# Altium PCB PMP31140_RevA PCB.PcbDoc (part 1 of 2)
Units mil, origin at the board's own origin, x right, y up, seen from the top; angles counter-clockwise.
Board outline 6181.25 x 1625 mil, 2 copper layers (Top Layer, Bottom Layer), stack 62 mil thick; 98 components, 49 nets, 210 pads, 6 vias.
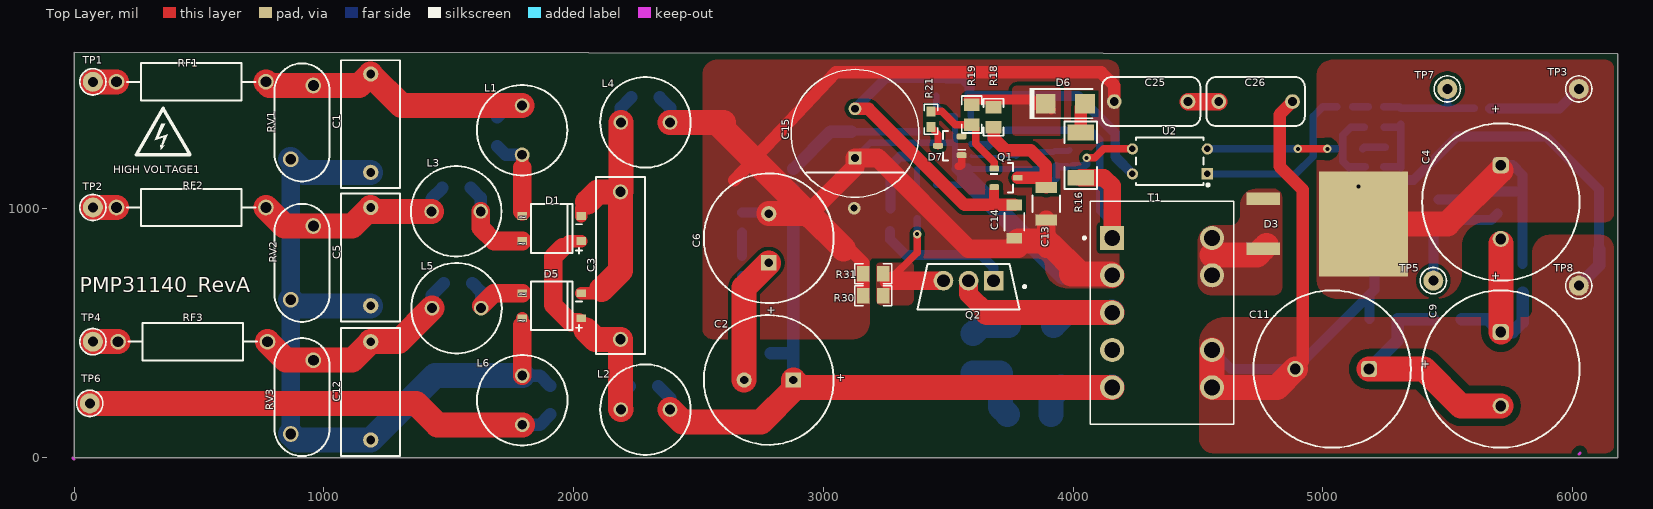
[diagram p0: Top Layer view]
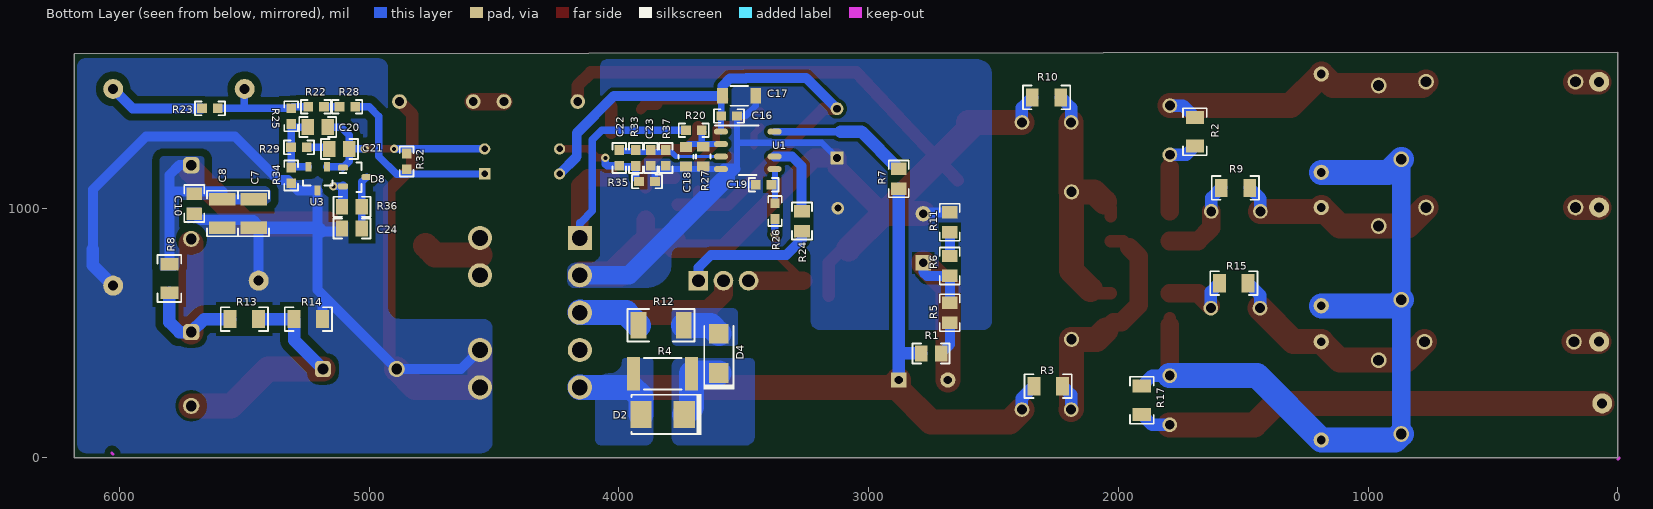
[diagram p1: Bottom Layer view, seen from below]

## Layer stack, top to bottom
Top Solder: solder mask 0.4, Solder Resist, Dk 3.5
Top Layer: signal copper 1.4
Dielectric1: core 59.2, FR-4, Dk 4.8
Bottom Layer: signal copper 1.4
Bottom Solder: solder mask 0.4, Solder Resist, Dk 3.5

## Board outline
0,0 0,1625 6181.25,1618.75 6181.25,1617.36 6181.25,0

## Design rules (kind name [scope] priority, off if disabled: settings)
AcuteAngle [All] p1: minimum=4.50000000000000E+0001 checktracksonly=FALSE
AssemblyTestPointUsage [All] p1: valid=2
Clearance "Schematic Clearance Constraint" [InNet('NetC3_1')] p1: gap=25 ignorepadtopadclearanceinfootprint=FALSE except(0: Arc-Hole Track-Hole SMDPad-Hole THPad-Hole Via-Hole Fill-Hole Poly-Hole Region-Hole Text-Hole)
Clearance "Clearance_PGND NETC17_2" [InNet('PGND') vs InNet('NetC17_2')] p2: gap=10 ignorepadtopadclearanceinfootprint=FALSE
Clearance "Clearance_PGND NETC9_1" [InNet('PGND') vs InNet('NetC13_2')] p3: gap=5 ignorepadtopadclearanceinfootprint=FALSE
Clearance Clearance_PGND [InNet('PGND')] p4: gap=15 ignorepadtopadclearanceinfootprint=FALSE
Clearance Clearance_Keepouts [((IsTrack Or IsArc) And Not InPoly) And IsFree and IsKeepOut vs ((IsTrack Or IsArc) And Not InPoly) And IsFree and IsKeepOut] p5: gap=0 ignorepadtopadclearanceinfootprint=FALSE
Clearance Clearance_BoardEdge_MountingHoles [OnCopper and InComponentClass('Mounting Holes') vs IsKeepOut] p6: gap=40 ignorepadtopadclearanceinfootprint=FALSE except(0: Arc-Hole Track-Hole SMDPad-Hole THPad-Hole Via-Hole Fill-Hole Poly-Hole Region-Hole Text-Hole)
Clearance Clearance_BoardEdge_Poly [OnCopper and InPoly vs IsKeepOut] p7: gap=25 ignorepadtopadclearanceinfootprint=FALSE except(0: Arc-Hole Track-Hole SMDPad-Hole THPad-Hole Via-Hole Fill-Hole Poly-Hole Region-Hole Text-Hole)
Clearance Clearance_BoardEdge [OnCopper and Not InComponentClass('Logo') and not InComponentClass('FiducialMark') and not InRegion(1000,500,4000,800) and Not IsKeepout vs IsKeepOut] p8: gap=75 ignorepadtopadclearanceinfootprint=FALSE except(0: Arc-Hole Track-Hole SMDPad-Hole THPad-Hole Via-Hole Fill-Hole Poly-Hole Region-Hole Text-Hole)
Clearance Clearance_Poly [InPolygon] p9: gap=30 ignorepadtopadclearanceinfootprint=FALSE
Clearance [All] p10: gap=7 ignorepadtopadclearanceinfootprint=FALSE
ComponentClearance ComponentClearance_104 [InComponent('TP104')] p1: gap=1 collisioncheckmode=3 verticalgap=1 showdistances=FALSE
ComponentClearance ComponentClearance_103 [InComponent('TP103')] p2: gap=1 collisioncheckmode=3 verticalgap=1 showdistances=FALSE
ComponentClearance ComponentClearance_102 [InComponent('TP102')] p3: gap=1 collisioncheckmode=3 verticalgap=1 showdistances=FALSE
ComponentClearance ComponentClearance_TP101 [InComponent('TP101')] p4: gap=1 collisioncheckmode=3 verticalgap=1 showdistances=FALSE
ComponentClearance ComponentClearance_MountingHoles_FiducialMarks [InComponentClass('Mounting Holes') vs InComponentClass('FiducialMark')] p5: gap=50 collisioncheckmode=3 verticalgap=10 showdistances=FALSE
ComponentClearance ComponentClearance_Shunt [InComponentClass('Header') vs InComponentClass('Shunt')] p6: gap=0 collisioncheckmode=3 verticalgap=0 showdistances=FALSE
ComponentClearance ComponentClearance_Logo [InComponentClass('Logo')] p7: gap=50 collisioncheckmode=3 verticalgap=10 showdistances=FALSE
ComponentClearance ComponentClearance_ScrewToNut [(HasFootprint('NY PMS 440 0025 PH')) vs (HasFootprint('Keystone_1902C'))] p8: gap=5 collisioncheckmode=3 verticalgap=10 showdistances=FALSE
ComponentClearance ComponentClearance_MountingHoles [InComponentClass('Mounting Holes')] p9: gap=250 collisioncheckmode=3 verticalgap=100000 showdistances=FALSE
ComponentClearance ComponentClearance_SmallPassives [HasFootprint('0201*') or HasFootprint('0402*') or HasFootprint('0508') or HasFootprint('0603*') or HasFootprint('0612') or HasFootprint('0805*') or HasFootprint('0815*') or HasFootprint('0830*') or HasFootprint('1206*') or HasFootprint('1210*') or HasFootprint('1808*') or HasFootprint('1812*') or HasFootprint('1825*') or HasFootprint('2010*') or HasFootprint('2220*') or HasFootprint('2225*') or HasFootprint('2512*') or HasFootprint('2728*') or HasFootprint('3518*') vs HasFootprint('0201*') or HasFootprint('0402*') or HasFootprint('0508') or HasFootprint('0603*') or HasFootprint('0612') or HasFootprint('0805*') or HasFootprint('0815*') or HasFootprint('0830*') or HasFootprint('1206*') or HasFootprint('1210*') or HasFootprint('1808*') or HasFootprint('1812*') or HasFootprint('1825*') or HasFootprint('2010*') or HasFootprint('2220*') or HasFootprint('2225*') or HasFootprint('2512*') or HasFootprint('2728*') or HasFootprint('3518*')] p10: gap=10 collisioncheckmode=3 verticalgap=10 showdistances=FALSE
ComponentClearance ComponentClearance_THtoSMT [IsThruComponent vs IsSMTComponent] p11: gap=20 collisioncheckmode=3 verticalgap=30 showdistances=FALSE
ComponentClearance ComponentClearance_THtoTH [IsThruComponent vs IsThruComponent] p12: gap=20 collisioncheckmode=3 verticalgap=30 showdistances=FALSE
ComponentClearance [All] p13: gap=20 collisioncheckmode=3 verticalgap=10 showdistances=FALSE
DiffPairsRouting [All] p1: maxlimit=100 minlimit=10 mostfreqgap=10 toplayer_minwidth=15 toplayer_maxwidth=15 toplayer_prefwidth=15 bottomlayer_minwidth=15 bottomlayer_maxwidth=15 bottomlayer_prefwidth=15 maxuncoupledlength=1000
FabricationTestPointUsage TestPointUsage [All] p1: valid=2 allowmultiple=FALSE
FabricationTestpoint Testpoint [All] p1: side=3 testpointundercomponent=TRUE minsize=40 maxsize=100 preferedsize=60 minholesize=0 maxholesize=40 preferedholesize=32 testpointgrid=1 allowsidetop=TRUE allowsidebottom=TRUE usegrid=TRUE gridtolerance=0.01
FanoutControl Fanout_LCC [IsLCC] p1: bgadir=Out bgaviamode=Centered fanoutstyle=Auto fanoutdirection=Alternating viagrid=1 // Fanout_LCC (Default Rule)
FanoutControl Fanout_BGA [IsBGA] p2: bgadir=Out bgaviamode=Centered fanoutstyle=Auto fanoutdirection=Alternating viagrid=1 // Fanout_BGA (Default Rule)
FanoutControl Fanout_Default [All] p4: bgadir=Out bgaviamode=Centered fanoutstyle=Auto fanoutdirection=Alternating viagrid=1 // Fanout_Default (Default Rule)
FanoutControl Fanout_Small [(CompPinCount < 5)] p5: bgadir=Out bgaviamode=Centered fanoutstyle=Auto fanoutdirection=OutThenIn viagrid=1 // Fanout_Small (Default Rule)
Height [All] p1: minheight=0 maxheight=2000 prefheight=500
HoleSize [All] p1: absolutevalues=TRUE maxlimit=251 minlimit=8 maxpercent=80.000 minpercent=20.000
MinimumAnnularRing MinimumAnnularRing_ThermalPadVias [IsVia and InAnyComponent] p1: minimumring=5.91
MinimumAnnularRing [All] p2: minimumring=9
MinimumSolderMaskSliver MinimumSolderMaskSliver_Logo [InComponentClass('Logo') vs InComponentClass('Logo')] p1: minsoldermaskwidth=0.7
MinimumSolderMaskSliver [All] p2: minsoldermaskwidth=3.94
PlaneConnect [All] p1: planeconnectstyle=Direct reliefexpansion=10 reliefentries=4 reliefconductorwidth=10 reliefairgap=10
PolygonConnect [All] p1: connectstyle=Direct reliefconductorwidth=10 reliefentries=4 polygonreliefangle="90 Angle" airgapwidth=10
RoutingVias ThermalPadVias [IsVia and InAnyComponent] p1: holewidth=7.87 width=19.68 viastyle="Through Hole" minholewidth=7.87 minwidth=19.68 maxholewidth=12.99 maxwidth=23.62
RoutingVias [All] p2: holewidth=16 width=34 viastyle="Through Hole" minholewidth=7.87 minwidth=26 maxholewidth=40 maxwidth=65
SilkToBoardRegionClearance [Not ((IsComment or IsDesignator) And (Hide <> 'False')) and not InRegion(1000,500,4000,800)] p1:
SilkToSilkClearance SilkToSilkClearance_Pb-FreeLogo [(HasFootprint('Pb-Free_Overlay_Medium') OR HasFootprint('Pb-Free_Overlay_Small')) vs (HasFootprint('Pb-Free_Overlay_Medium') OR HasFootprint('Pb-Free_Overlay_Small'))] p1: silktosilkclearance=0
SilkToSilkClearance [All] p2: silktosilkclearance=0
SilkToSolderMaskClearance SilkToComonentPadClearance [IsPad and InAnycomponent] p1: minsilkscreentomaskgap=0 clearancetoexposedcopper=TRUE
SilkToSolderMaskClearance "Silk to Solder Mask Opening" [All] p2: minsilkscreentomaskgap=4 clearancetoexposedcopper=FALSE
SolderMaskExpansion [All] p1: expansion=1.97 istentingtop=FALSE
Width [All] p1: maxlimit=200 minlimit=6 preferedwidth=10 checkconnectedcopper=TRUE
14 further rules are at their usual default settings.

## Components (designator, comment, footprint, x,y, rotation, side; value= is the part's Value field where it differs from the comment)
C1 "B32921C3104M" B32921_1300x1200x600 1187.5,1340.6 r270 top value=DNP
C2 "EKXG401ELL220MK20S" KXG_1250x2000 2781.25,312.5 r180 top value=22uF
C3 "B32652A0103K" B32652A_500x1050x1800 2187.5,770.28 r90 top value=0.01uF
C4 "SCCU25B256SRB" SCC_1600x2650 5712.5,1024.85 r270 top value=25F
C5 "B32921C3104M" B32921_1300x1200x600 1187.5,806.25 r270 top value=DNP
C6 "EKXG401ELL220MK20S" KXG_1250x2000 2781.25,879.68 r90 top value=22uF
C7 "GRM32ER71A476KE15L" 1210_270 5462.5,978.75 r270 bottom value=47uF
C8 "GRM32ER71A476KE15L" 1210_270 5587.5,978.75 r270 bottom value=47uF
C9 "SCCU25B256SRB" SCC_1600x2650 5712.5,356.25 r270 top value=25F
C10 "GRM21BR71C105KA01L" 0805_HV 5700,1018.75 r270 bottom value=1uF
C11 "SCCU25B256SRB" SCC_1600x2650 5037.5,356.25 r180 top value=25F
C12 "B32921C3104M" B32921_1300x1200x600 1187.5,268.75 r270 top value=DNP
C13 "C3225X7R1H475K250AB" 1210_280 3892.68,1018.19 r270 top value=4.7uF
C14 "C3216X7R1H475K160AC" 1206_180 3764.38,946.49 r270 top value=DNP
C15 "ECA-1HM102" FP-ECA-1HM102_RADIAL-MFG 3126.74,1299.89 r90 top
C16 "06035C104KAT2A" 0603 3558.96,1369.34 r180 bottom value=0.1uF
C17 "C3216X7R1H475K160AC" 1206_180 3518.75,1450 r180 bottom value=2.2uF
C18 "DNP" 0805_HV1 3731.5,1206.25 r270 bottom
C19 "Used in BOM report" 0603 3420.51,1094.34 r0 bottom value=DNP
C20 "CC0805KRX7R9BB682" 0805_HV 5206.25,1325 r180 bottom value=6800pF
C21 "Used in BOM report" 0805_HV 5119,1237.5 r0 bottom value=DNP
C22 "06035C333JAT2A" 0603 3998.28,1201.46 r90 bottom value=0.047uF
C23 "GRM188R71H222KA01D" 0603 3872.51,1201.46 r270 bottom value=2200pF
C24 "GRM21BR71E105KA99L" 0805_HV 5068.75,918.75 r0 bottom value=2.2uF
C25 "DE2E3KY472MB3BM02F" KY_1000x500x1300 4312.5,1427.1 r180 top value=4700pF
C26 "DE2E3KY472MB3BM02F" KY_1000x500x1300 4730.84,1427.1 r180 top value=4700pF
D1 "MB8S-TP" MBS-1 1912.5,918.75 r180 top value=800V
D2 "Used in BOM report" SMB 3825,175 r0 bottom value=130V
D3 "STPS8H100G-TR" DDPAK 5006.99,937.5 r0 top value=100V
D4 "US1K-13-F" SMA 3600,418.75 r90 bottom value=800V
D5 "MB8S-TP" MBS-1 1912.5,609.4 r180 top value=800V
D6 "ES1D-13-F" SMA 3968.75,1418.75 r0 top value=200V
D7 "MMBZ5248BLT1G" SOT-23 3506.25,1250 r180 top value=18V
D8 "BAT54S-7-F" SOT-23 5057.7,1125 r180 bottom value=30V
"HIGH VOLTAGE1" "DANGER HIGH VOLTAGE" IEC_HighVoltage_Small 356.25,1302.51 r0 top
L1 "744732331" WE-TI_8075_STU 1793.75,1312.5 r270 top value=SHORT
L2 "744732331" WE-TI_8075_STU 2287.5,193.75 r0 top value=330uH
L3 "744732331" WE-TI_8075_STU 1529.68,987.5 r0 top value=SHORT
L4 "744732331" WE-TI_8075_STU 2287.5,1343.75 r0 top value=330uH
L5 "744732331" WE-TI_8075_STU 1531.25,600 r0 top value=SHORT
L6 "744732331" WE-TI_8075_STU 1794.39,231.25 r90 top value=SHORT
Q1 "FMMT451" SOT-23 3731.25,1121.95 r0 top value="60 V"
Q2 "STP7N105K5" FP-STP7N105K5_TO-220AB-MFG 3581.25,685.93 r270 top
R1 "CRCW08051M50JNEA" 0805_HV 2750,418.75 r0 bottom value=2.0Meg
R2 "CRCW120610K0JNEA" 1206 1693.75,1306.25 r270 bottom value=DNP
R3 "CRCW120610K0JNEA" 1206 2281.25,287.5 r0 bottom value=10k
R4 "Used in BOM report" 2512 3825,337.5 r0 bottom value=DNP
R5 "CRCW08051M50JNEA" 0805_HV 2675,581.25 r270 bottom value=2.0Meg
R6 "CRCW08051M50JNEA" 0805_HV 2675,768.75 r270 bottom value=2.0Meg
R7 "CRCW080530K0JNEA" 0805_HV 2879.68,1117.59 r270 bottom value=0
R8 "CRCW12061K00JNEA" 1206 5800,718.75 r90 bottom value=1.0k
R9 "CRCW120610K0JNEA" 1206 1531.25,1081.25 r0 bottom value=DNP
R10 "CRCW120610K0JNEA" 1206 2287.5,1443.75 r0 bottom value=10k
R11 "CRCW08051M50JNEA" 0805_HV 2675,943.75 r270 bottom value=2.0Meg
R12 "CRCW2010200RFKEF" 2010 3831.25,531.25 r180 bottom value=200
R13 "CRCW12061K00JNEA" 1206 5500,556.25 r0 bottom value=1.0k
R14 "CRCW12061K00JNEA" 1206 5243.65,556.25 r0 bottom value=1.0k
R15 "CRCW120610K0JNEA" 1206 1537.5,700 r0 bottom value=DNP
R16 "CRCW2010100RJNEF" 2010 4031.25,1212.5 r90 top value=100
R17 "CRCW120610K0JNEA" 1206 1906.25,231.25 r90 bottom value=DNP
R18 "CRCW080510R0FKEA" 0805_HV 3681.64,1364.55 r90 top value=10.0
R19 "CRCW0805200KFKEA" 0805_HV 3593.75,1375 r90 top value=200k
R20 "CRCW0603348KFKEA" 0603 3700,1312.5 r0 bottom value=348k
R21 "Used in BOM report" 0603 3431.25,1356.5 r90 top value=0
R22 "CRCW06030000Z0EA" 0603 5212.5,1406.25 r0 bottom value=0
R23 "CRCW060349R9FKEA" 0603 5637.5,1400 r180 bottom value=49.9
R24 "RC0805FR-0710RL" 0805_HV 3266.96,948.72 r270 bottom value=10.0
R25 "CRCW060349K9FKEA" 0603 5312.5,1368.75 r90 bottom value=49.9k
R26 "CRCW06031K69FKEA" 0603 3375,988.72 r270 bottom value=1.69k
R27 "CRCW080556K2FKEA" 0805_HV1 3662.5,1206.84 r270 bottom value=56.2k
R28 "CRCW06031K50FKEA" 0603 5087.5,1406.25 r0 bottom value=1.50k
R29 "Used in BOM report" 0603 5281.25,1243.75 r180 bottom value=DNP
R30 "ERJ-6RQF2R2V" 0805_HV 3200,650 r0 top value=2.20
R31 "ERJ-6RQF2R2V" 0805_HV 3200,737.5 r0 top value=2.20
R32 "Used in BOM report" 0603 4850,1187.36 r270 bottom value=DNP
R33 "CRCW060330K1FKEA" 0603 3931.99,1201.09 r270 bottom value=100k
R34 "CRCW060330K9FKEA" 0603 5312.5,1131.25 r90 bottom value=30.9k
R35 "Used in BOM report" 0603 3887.5,1107.32 r180 bottom value=DNP
R36 "CRCW0805100KFKEA" 0805_HV 5068.75,1006.25 r180 bottom value=100k
R37 "CRCW060310K0FKEA" 0603 3812.5,1201.46 r90 bottom value=22.1k
RF1 "SPP1UL1R00JLF" SPP_1020x380 468.75,1506.25 r180 top value=1.0
RF2 "SPP1UL1R00JLF" SPP_1020x380 468.75,1003.1 r180 top value=1.0
RF3 "SPP1UL1R00JLF" SPP_1020x380 475,465.6 r180 top value=1.0
RV1 "B72210S2301K101" EPCOS_B72210S2301K101 912.5,1343.75 r90 top value=300VAC
RV2 "B72210S2301K101" EPCOS_B72210S2301K101 912.5,781.25 r90 top value=300VAC
RV3 "B72210S2301K101" EPCOS_B72210S2301K101 912.5,243.75 r90 top value=300VAC
T1 "750319952r00" FP-750319952r00_PTH10_14MM6_22MM7-MFG 4356.25,581.85 r0 top
TP1 "5000" Keystone5000 75,1506.25 r90 top
TP2 "5000" Keystone5000 75,1003.1 r90 top
TP3 "5000" Keystone5000 6025,1477.67 r90 top
TP4 "5000" Keystone5000 75,465.6 r90 top
TP5 "5001" Keystone5001 5442.31,710.05 r0 top
TP6 "5000" Keystone5000 62.5,218.75 r90 top
TP7 "5000" Keystone5000 5498.47,1477.67 r90 top
TP8 "5001" Keystone5001 6025,690.13 r90 top
U1 "UCC28740DR" D0007A_N 3483.96,1231.84 r180 bottom
U2 "FOD817A" DIP-4 4387.5,1187.5 r180 top
U3 "ATL431LIBQDBZR" DBZ0003A_N 5206.25,1118.75 r270 bottom

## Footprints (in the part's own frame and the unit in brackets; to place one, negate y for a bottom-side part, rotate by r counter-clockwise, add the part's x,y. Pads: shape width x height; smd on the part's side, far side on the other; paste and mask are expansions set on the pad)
0603 [mm] "0603 from SM-752 data"
  rect 1x0.95 smd: 1(-0.8,0) 2(0.8,0)
  silkscreen extent -1.52,-0.69 1.52,0.69, body extent -0.87,-0.47 0.87,0.47, height 1
0805_HV [mil] "0805 with 30mil clearance between pads"
  rect 50x63 smd: 1(-40,0) 2(40,0)
  silkscreen extent -74,-40 74,40, body extent -43,-29 43,29, height 57
0805_HV1 [mm] "Custom footprint based on analyzing multiple manufacturer recommendations"
  rrect10% 1x1.25 smd: 1(-1,0) 2(1,0)
  silkscreen extent -0.2,-0.75 0.2,0.75, body extent -1.1,-0.72 1.1,0.73, height 1.45
1206 [mm] "1206 from SM-752 data"
  rect 1.3x1.85 smd: 1(-1.45,0) 2(1.45,0)
  silkscreen extent -2.4,-1.21 2.4,1.21, body extent -1.7,-0.9 1.7,0.9, height 1.35
1206_180 [mm] "1206_180"
  rect 1.1x1.6 smd: 1(-1.7,0) 2(1.7,0)
  silkscreen extent -0.9,-1 0.9,1, body extent -1.75,-0.95 1.75,0.95, height 1.8
1210_270 [mm] "1210"
  rect 1.3x2.7 smd: 1(-1.45,0) 2(1.45,0)
  silkscreen extent -2.32,-1.57 2.32,1.57, body extent -1.7,-1.35 1.7,1.35, height 2.7
1210_280 [mm] "SMD, 2-Leads, Body 3.6x2.8mm, Height 2.8mm"
  rect 1.1x2.2 smd: 1(-1.65,0) 2(1.65,0)
  silkscreen extent -0.84,-1.4 0.84,1.4, body extent -1.8,-1.4 1.8,1.4, height 2.8
2010 [mm] "Chip Capacitor, Body 5.08x2.54mm, IPC Medium Density"
  rect 1.6x2.7 smd: 1(-2.3,0) 2(2.3,0)
  silkscreen extent -3.42,-1.65 3.42,1.65, body extent -2.73,-1.45 2.73,1.45, height 1.66
2512 [mm] "Chip Resistor, Body 6.3x3.2mm, IPC Medium Density"
  rect 1.3x3.4 smd: 1(-2.95,0) 2(2.95,0)
  silkscreen extent -1.9,-1.6 1.9,1.6, body extent -3.22,-1.67 3.22,1.67, height 0.71
B32652A_500x1050x1800 [mm] "THD, 2-Leads, Body 18x5mm, Height 10.5mm"
  round 1.55 hole 1.05: 1(-7.5,0) 2(7.5,0)
  silkscreen extent -9,-2.5 9,2.5, body extent -9,-2.5 9,2.5, height 10.5
B32921_1300x1200x600 [mm] "EPCOS"
  round 1.55 hole 0.9: 1(-5,0) 2(5,0)
  silkscreen extent -6.4,-3 6.6,3, body extent -6.4,-3 6.6,3, height 12
D0007A_N [mm] "SOIC, 7-Leads, Body 4.9x3.9mm, Pitch 1.27mm, IPC Medium Density"
  oval 1.45x0.6 smd: 1(-2.725,1.905) 2(-2.725,0.635) 3(-2.725,-0.635) 4(-2.725,-1.905) 5(2.725,-1.905) 6(2.725,-0.635) 8(2.725,1.905)
  silkscreen extent -3.32,-2.5 1.1,2.52, body extent -3.01,-2.45 3.01,2.45, height 1.75
DBZ0003A_N [mm] "SOT23, 3-Leads, Body 2.9x1.3mm, Pitch 0.95mm, Lead Span 2.4mm, IPC Medium Density"
  rrect17% 1x0.6 smd: 1(-1.2,0.95) 2(-1.2,-0.95) 3(1.2,0)
  silkscreen extent 0.2,-1.5 0.7,1.5, body extent -1.26,-1.46 1.26,1.46, height 0.98
DDPAK [mil] "D2-PAK, 3-Pads, Body 9.7x10.4mm (max), TO-263AB, using Vishay Silionix recommended pad sizes"
  rrect8% 135x49.49 smd: 1(-246.06,100) 3(-246.06,-100)
  rrect1% 355x420 smd paste-181.1: 2(155.51,0)
  body extent -295,-202 324,202, height 180
DIP-4 [mm] "DIP, 4-Leads, Body 6.86x4.83mm, Pitch 2.54mm"
  rect 1.15x1.15 hole 0.65: 1(-3.81,1.27)
  round 1.15 hole 0.65: 2(-3.81,-1.27) 3(3.81,-1.27) 4(3.81,1.27)
  silkscreen extent -4,-2.41 3.43,2.52, body extent -4.02,-2.41 4.02,2.41, height 5.59
EPCOS_B72210S2301K101 [mm] "Through Hole Varistor, 2-Leads, Body 12x5.6mm, Height 14.5mm"
  round 1.6 hole 1.1: 1(-3.75,1.15) 2(3.75,-1.15)
  silkscreen extent -6,-2.8 6,2.8, body extent -5.95,-2.8 6,2.8, height 14.49
FP-750319952r00_PTH10_14MM6_22MM7-MFG [mm]
  rrect4% 2.45x2.45 hole 1.6 paste-1000 mask+0: 1(-5.08,7.6)
  round 2.45 hole 1.6 paste-1000 mask+0: 2(-5.08,3.8) 3(-5.08,0) 4(-5.08,-3.8) 5(-5.08,-7.6) 6(5.08,-7.6) 7(5.08,-3.8) 9(5.08,3.8) 10(5.08,7.6)
  silkscreen extent -8.02,-11.35 7.3,11.35, body extent -7.4,-11.45 7.4,11.45, height 0.25
FP-ECA-1HM102_RADIAL-MFG [mm]
  rrect8% 1.3x1.3 hole 0.8 paste-1000 mask+0: 1(-2.5,0)
  round 1.3 hole 0.8 paste-1000 mask+0: 2(2.5,0)
  silkscreen extent -6.5,-6.5 6.5,6.5, body extent -6.6,-6.6 6.6,6.6, height 0.25
FP-STP7N105K5_TO-220AB-MFG [mm]
  rrect5% 2x2 hole 1.3 paste-1000 mask+0: 1(-0.605,2.55)
  round 2 hole 1.3 paste-1000 mask+0: 2(-0.605,0) 3(-0.605,-2.55)
  silkscreen extent -2.3,-5.2 2.3,5.82, body extent -2.4,-5.3 2.4,5.3, height 0.25
IEC_HighVoltage_Small [mil]
  silkscreen extent -107,-88 107,97
Keystone5000 [mil] "For Keystone 500x miniature loop terminals"
  round 80 hole 40: 1(0,0)
  silkscreen extent -52,-52 52,52, body extent -49,-49 49,49, height 182
Keystone5001 [mil] "For Keystone 500x miniature loop terminals"
  round 80 hole 40: 1(0,0)
  silkscreen extent -52,-52 52,52, body extent -49,-49 49,49, height 182
KXG_1250x2000 [mm] "United Chemicon"
  rect 1.55x1.55 hole 0.85: 1(-2.5,0)
  round 1.55 hole 0.85: 2(2.5,0)
  silkscreen extent -6.6,-6.6 6.6,6.6, body extent -6.45,-6.49 6.49,6.49, height 21.51
KY_1000x500x1300 [mm] "MuRata"
  round 1.5 hole 0.9: 1(-3.75,0) 2(3.75,0)
  silkscreen extent -5,-2.5 5,2.5, body extent -5,-2.5 5,2.5, height 13
MBS-1 [mm] "SOP, 4-Leads, Body 4.95x4.2mm"
  rect 1x0.8 smd: 1(-3,1.27) 2(3,1.27) 3(3,-1.27) 4(-3,-1.27)
  silkscreen extent -3.08,-2.48 2.1,2.56, body extent -3.45,-2.47 3.45,2.48, height 2.9
SCC_1600x2650 [mm] "TH, 2-Leads, Dia 16mm, Pin Spacing 7.5mm"
  rrect50% 1.65x1.65 hole 1.1: 1(-3.75,0)
  round 1.65 hole 1.1: 2(3.75,0)
  silkscreen extent -8,-8 8,8, body extent -8,-8 8.01,8, height 26.51
SMA [mm] "Molded Diode, 2-Leads, Body 4.3x2.6mm, IPC Medium Density, based on OnSemi component dimensions and land pattern"
  rect 2x2 smd: 1(-2,0) 2(2,0)
  silkscreen extent -3.66,-1.57 2.79,1.57, body extent -2.6,-1.3 2.6,1.3, height 2.42
SMB [mil] "Molded Diode, 2-Leads, Body 5.4x3.6mm, IPC Medium Density, based on OnSemi component dimensions"
  rect 85x107.99 smd: 1(-87.01,0) 2(87.01,0)
  silkscreen extent -155,-82 125,82, body extent -106,-71 106,71, height 91
SOT-23 [mm] "SOT23, 3-Leads, Body 2.9x1.3mm, Pitch 0.95mm, Lead Span 2.5mm, IPC Medium Density"
  rrect50% 1x0.6 smd: 1(-1.2,0.95) 2(-1.2,-0.95) 3(1.2,0)
  silkscreen extent -1.62,-1.5 0.7,1.5, body extent -1.16,-1.45 1.21,1.45, height 1
SPP_1020x380 [mm] "TH, 2-Leads, Axial, Dia 3.8mm, Pin Spaing 15.2mm"
  round 1.6 hole 1.1: 1(-7.6,0) 2(7.6,0)
  silkscreen extent -6.53,-1.9 6.53,1.9, body extent -8,-1.88 8,1.9, height 3.8
WE-TI_8075_STU [mm] "TH, 2-Leads, Dia 9.5mm, Pin Spacing 5mm"
  round 1.5 hole 1: 1(-2.5,0) 2(2.5,0)
  silkscreen extent -4.6,-4.6 4.6,4.6, body extent -5.8,-5.8 5.8,5.8, height 9.7

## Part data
C1 C5 C12: library part CMP-0012393-1, "CAP, Film, 0.1 uF, 305 V, +/- 20%, TH", Cap_Case=13x12x6mm, Manufacturer=TDK, Supplier Part Number 1=495-2318-ND, Tolerance_%=20%, Value1=Unknown, Value2=305V, ValueDisplayed=0.1uF
C2 C6: library part CMP-0010039-1, "CAP, AL, 22 uF, 400 V, +/- 20%, TH", Cap_Case=12.5x20, Manufacturer=Chemi-Con, Supplier Part Number 1=565-1463-ND, Tolerance_%=20%, Value1=Unknown, Value2=400V, ValueDisplayed=22uF
C3: library part CMP-0012344-3, "CAP, Film, 0.01 uF, 1000 V, +/- 10%, TH", Cap_Case=5x10.5x18, Manufacturer=TDK, Tolerance_%=10%, Value1=Unknown, Value2=1000V, ValueDisplayed=0.01uF
C4 C9 C11: library part CMP-0860272-1, "CAP, Electric Double Layer, 25000000 µF, 2.7 V,+30/--10%, 0.027 ohm, TH", Cap_Case=16x25mm, Manufacturer=AVX, Tolerance_%=30%, Value1="0.027 ohm", Value2=2.7V, ValueDisplayed=25000000µF
C7 C8: library part CMP-0009220-2, "CAP, CERM, 47 uF, 10 V, +/- 10%, X7R, 1210", Cap_Case=1210, Manufacturer=MuRata, Supplier Part Number 1=490-5312-1-ND, TempCo=X7R, Tolerance_%=10%, Value1=Unknown, Value2=10V, ValueDisplayed=47uF
C10: library part CMP-0008323-1, "CAP, CERM, 1 uF, 16 V, +/- 10%, X7R, 0805", Cap_Case=0805, Manufacturer=MuRata, Supplier Part Number 1=490-1691-1-ND, TempCo=X7R, Tolerance_%=10%, Value1="0.003 ohm", Value2=16V, ValueDisplayed=1uF
C13: library part CMP-0009124-1, "CAP, CERM, 4.7 uF, 50 V, +/- 10%, X7R, 1210", Cap_Case=1210_280, Manufacturer=TDK, Supplier Part Number 1=445-7726-1-ND, TempCo=X7R, Tolerance_%=10%, Value1="0.003166 ohm", Value2=50V, ValueDisplayed=4.7uF
C14: library part C2012X7R1H225K125AC, "CAP, CERM, 2.2 µF, 50 V,+/- 10%, X7R, 0805", Cap_Case=0805, Manufacturer=TDK, PartNumber=DNP, Supplier Part Number 1=445-5968-1-ND, TempCo=X7R, Tolerance_%=10, Value1="0.00366 ohm", Value2=50V
C15: library part CMP-0088449-1, "1000µF 50V Aluminum Electrolytic Capacitors Radial", Digikey Part Number=860010678024, Leakage Current=500uA, Operating Temperature Range="-40°C to +85°C", Supplier Part Number 1=P5186-ND, Tolerance_%=20%, ValueDisplayed=1000uF, Voltage=50V
C16: "CAP, CERM, 0.1 µF, 50 V, +/- 10%, X7R, 0603", Cap_Case=0603, Manufacturer=AVX, Supplier Part Number 1=478-5052-1-ND, TempCo=X7R, Tolerance_%=10, Value1=Unknown, Value2=50V, ValueDisplayed=0.1µF
C17: library part C2012X7R1H225K125AC, "CAP, CERM, 2.2 µF, 50 V,+/- 10%, X7R, 0805", Cap_Case=0805, Manufacturer=TDK, Supplier Part Number 1=445-5968-1-ND, TempCo=X7R, Tolerance_%=10, Value1="0.00366 ohm", Value2=50V, ValueDisplayed=2.2µF
C18: library part 08051C103KAT2A, "CAP, CERM,", Cap_Case=0805
C19 C21: library part Capacitor, "CAP, CERM, xxxF, xxV, [TempCo], xx%, [PackageReference]", Alternate Manufacturer=-
C20: library part CMP-0007957-2, "CAP, CERM, 6800 pF, 50 V, +/- 10%, X7R, 0805", Cap_Case=0805, Manufacturer="Yageo America", Supplier Part Number 1=311-1135-1-ND, TempCo=X7R, Tolerance_%=10%, Value1=Unknown, Value2=50V, ValueDisplayed=6800pF
C22: library part C1608X7R1H473K080AA, "CAP, CERM, 0.047 µF, 50 V,+/- 10%, X7R, 0603", Cap_Case=0603, Manufacturer=TDK, Supplier Part Number 1=445-1313-1-ND, TempCo=X7R, Tolerance_%=10, Value1="0.049007 ohm", Value2=50V, ValueDisplayed=0.047µF
C23: "CAP, CERM, 2200 pF, 50 V,+/- 10%, X7R, 0603", Cap_Case=0603, Manufacturer=MuRata, Supplier Part Number 1=490-1500-1-ND, TempCo=X7R, Tolerance_%=10, Value2=50V, ValueDisplayed=2200pF
C24: library part GRM21BR71E225KA73L, "CAP, CERM, 2.2 µF, 25 V,+/- 10%, X7R, 0805", Cap_Case=0805, Manufacturer=MuRata, Supplier Part Number 1=490-3331-1-ND, TempCo=X7R, Tolerance_%=10, Value1="0.005 ohm", Value2=25V, ValueDisplayed=2.2µF
C25 C26: "CAP, CERM, 4700 pF, X1 250 VAC/Y2 300 VAC, +/- 20%, E, 10x5x13mm", Cap_Case=10x5x13mm, Manufacturer=MuRata, Supplier Part Number 1=490-9484-ND, TempCo=E, Tolerance_%=20, ValueDisplayed=4700pF
D1 D5: library part CMP-0029235-1, "Diode, Switching-Bridge, 800 V, 0.5 A, TO269AA", Manufacturer="Micro Commercial Components", Supplier Part Number 1=MB8S-TPMSDKR-ND, Value1=0.5A, Value2=1V
D2: library part SMBJ120A-13-F, "Diode, TVS, Uni, 130 V, 193 Vc, SMB", Manufacturer="Diodes Inc.", PartNumber=SMBJ130A-13-F, Power_W=5, Supplier Part Number 1=SMBJ120A-FDICT-ND, Value1=5W
D3: library part CMP-0028896-2, "Diode, Schottky, 100 V, 8 A, DDPAK", Manufacturer=STMicroelectronics, Supplier Part Number 1=497-7571-1-ND, Value1=8A, Value2=0.71V
D4: "Diode, Fast Rectifier, 800 V, 1 A, SMA", Manufacturer="Diodes Inc.", Supplier Part Number 1=US1K-FDICT-ND, Value1=1A, Value2=1.7V
D6: "Diode, Ultrafast, 200 V, 1 A, SMA", Manufacturer="Diodes Inc.", Supplier Part Number 1=ES1D-FDICT-ND, Value1=1A, Value2=0.92V
D7: "Diode, Zener, 18 V, 225 mW, SOT-23", Manufacturer="ON Semiconductor", Power_W=0.225, Supplier Part Number 1=MMBZ5248BLT1GOSCT-ND, Value1=0.225W
D8: "Diode, Schottky, 30 V, 0.2 A, SOT-23", Manufacturer="Diodes Inc.", Supplier Part Number 1=BAT54S-FDICT-ND, Value1=0.2A, Value2=0.65V
"HIGH VOLTAGE1": library part IEC_HighVoltage, "IEC 61010-1 High Voltage Warning"
L1 L2 L3 L4 L5 L6: library part CMP-0064737-1, "Inductor, Unshielded Drum Core, Metal Composite, 330 uH", Manufacturer="Wurth Elektronik", Value1="2.2 ohm", ValueDisplayed=330uH
Q1: library part CMP-0000467-1, "Transistor, NPN, 60 V,", Manufacturer="Diodes Inc.", Value1="1.5 A", Value2=900
Q2: library part CMP-0088481-1, "N-Channel 1050V 4A (Tc) 110W (Tc) Through Hole TO-220", Digikey Part Number=497-15279-5-ND, Drain To Source Breakdown Voltage=1050V, Input Capacitace At Vds="380pF @ 100V", Manufacturer=STMicroelectronics, Mouser Part Number=511-STP7N105K5, Operating Temperature Range="-55°C to +150°C", Power_W=110W, Pulse Drain Current=16A
R1 R5 R6 R11: library part CRCW08052M00JNEA, "RES, 2.0 M, 5%, 0.125 W, 0805", Manufacturer=Vishay-Dale, Power_W=0.125, Supplier Part Number 1=541-2.0MACT-ND, TempCo="200 ppm/C", Tolerance_%=5, Value1=5%, Value2=0.125W, Value_Code=2M00, ValueDisplayed=2.0M
R2 R3 R9 R10 R15 R17: library part CMP-0018576-1, "RES, 10 k, 5%, 0.25 W, 1206", Manufacturer=Vishay-Dale, Power_W=250mW, Supplier Part Number 1=541-10KECT-ND, TempCo="200 ppm/C", Tolerance_%=5%, Value2=0.25W, Value_Code=10k0, ValueDisplayed=10k
R4 R29 R32 R35: library part Resistor, "RES, xxx ohm, x%, xW, [PackageReference]", Alternate Manufacturer=-
R7: "RES, 30 k, 5%, 0.125 W, 0805", Manufacturer=Vishay-Dale, Power_W=0.125, Supplier Part Number 1=541-30KACT-ND, TempCo="200 ppm/C", Tolerance_%=5, Value1=5%, Value2=0.125W, Value_Code=30k0, ValueDisplayed=0
R8 R13 R14: library part CMP-0018603-2, "RES, 1.0 k, 5%, 0.25 W, 1206", Manufacturer=Vishay-Dale, Power_W=250mW, Supplier Part Number 1=541-1.0KECT-ND, TempCo="200 ppm/C", Tolerance_%=5%, Value2=0.25W, Value_Code=1k00, ValueDisplayed=1.0k
R12: "RES, 200, 1%, 0.75 W, AEC-Q200 Grade 0, 2010", Manufacturer=Vishay-Dale, Power_W=0.75, Supplier Part Number 1=541-200ACCT-ND, TempCo="100 ppm/C", Tolerance_%=1, Value1=1%, Value2=0.75W, Value_Code=200R, ValueDisplayed=200
R16: "RES, 100, 5%, 0.75 W, AEC-Q200 Grade 0, 2010", Manufacturer=Vishay-Dale, Power_W=0.75, Supplier Part Number 1=541-100WCT-ND, TempCo="200 ppm/C", Tolerance_%=5, Value1=5%, Value2=0.75W, Value_Code=100R, ValueDisplayed=100
R18: library part CMP-0020847-3, "RES, 10.0, 1%, 0.125 W, AEC-Q200 Grade 0, 0805", Manufacturer=Vishay-Dale, Power_W=125mW, Supplier Part Number 1=541-10.0CCT-ND, TempCo="100 ppm/C", Tolerance_%=1%, Value2=0.125W, Value_Code=10R0, ValueDisplayed=10.0
R19: library part CMP-0021038-1, "RES, 200 k, 1%, 0.125 W, 0805", Manufacturer=Vishay-Dale, Power_W=125mW, Supplier Part Number 1=541-200KCCT-ND, TempCo="100 ppm/C", Tolerance_%=1%, Value2=0.125W, Value_Code=200k
R20: library part CMP-0022344-3, "RES, 348 k, 1%, 0.1 W, 0603", Manufacturer=Vishay-Dale, Power_W=100mW, Supplier Part Number 1=541-348KHCT-ND, TempCo="100 ppm/C", Tolerance_%=1%, Value2=0.1W, Value_Code=348k
R21: library part CRCW06030000Z0EA, "RES, 0, 5%, 0.1 W, 0603", Manufacturer=Vishay-Dale, Power_W=0.1, Supplier Part Number 1=541-0.0GCT-ND, TempCo="200 ppm/C", Tolerance_%=5, Value1=5%, Value2=0.1W, Value_Code=0000, ValueDisplayed=0
R22: "RES, 0, 5%, 0.1 W, 0603", Manufacturer=Vishay-Dale, Power_W=0.1, Supplier Part Number 1=541-0.0GCT-ND, TempCo="200 ppm/C", Tolerance_%=5, Value1=5%, Value2=0.1W, Value_Code=0000, ValueDisplayed=0
R23: "RES, 49.9, 1%, 0.1 W, 0603", Manufacturer=Vishay-Dale, Power_W=0.1, Supplier Part Number 1=541-49.9HCT-ND, TempCo="100 ppm/C", Tolerance_%=1, Value1=1%, Value2=0.1W, Value_Code=49R9, ValueDisplayed=49.9
R24: "RES, 10.0, 1%, 0.125 W, 0805", Manufacturer="Yageo America", Power_W=0.125, Supplier Part Number 1=311-10.0CRCT-ND, TempCo="200 ppm/C", Tolerance_%=1, Value1=1%, Value2=0.125W, Value_Code=10R0, ValueDisplayed=10.0
R25: library part CMP-0022447-3, "RES, 49.9 k, 1%, 0.1 W, 0603", Manufacturer=Vishay-Dale, Power_W=100mW, Supplier Part Number 1=541-49.9KHCT-ND, TempCo="100 ppm/C", Tolerance_%=1%, Value2=0.1W, Value_Code=49k9, ValueDisplayed=49.9k
R26: library part CMP-0022131-1, "RES, 1.69 k, 1%, 0.1 W, 0603", Manufacturer=Vishay-Dale, Power_W=100mW, Supplier Part Number 1=541-1.69KHCT-ND, TempCo="100 ppm/C", Tolerance_%=1%, Value2=0.1W, Value_Code=1k69, ValueDisplayed=1.69k
R27: library part CMP-0021334-2, "RES, 56.2 k, 1%, 0.125 W, 0805", Manufacturer=Vishay-Dale, Power_W=125mW, Supplier Part Number 1=541-56.2KCCT-ND, TempCo="100 ppm/C", Tolerance_%=1%, Value2=0.125W, Value_Code=56k2, ValueDisplayed=56.2k
R28: library part CMP-0022126-3, "RES, 1.50 k, 1%, 0.1 W, 0603", Manufacturer=Vishay-Dale, Power_W=100mW, Supplier Part Number 1=541-1.50KHCT-ND, TempCo="100 ppm/C", Tolerance_%=1%, Value2=0.1W, Value_Code=1k50, ValueDisplayed=1.50k
R30 R31: library part CMP-0021828-1, "RES, 2.20, 1%, 0.125 W, 0805", Manufacturer=Panasonic, Power_W=125mW, Supplier Part Number 1=P2.2DCT-ND, TempCo="200 ppm/C", Tolerance_%=1%, Value2=0.125W, Value_Code=2R20, ValueDisplayed=2.20
R33: library part CRCW0603100KFKEA, "RES, 100 k, 1%, 0.1 W, 0603", Manufacturer=Vishay-Dale, Power_W=0.1, Supplier Part Number 1=541-100KHCT-ND, TempCo="100 ppm/C", Tolerance_%=1, Value1=1%, Value2=0.1W, Value_Code=100k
